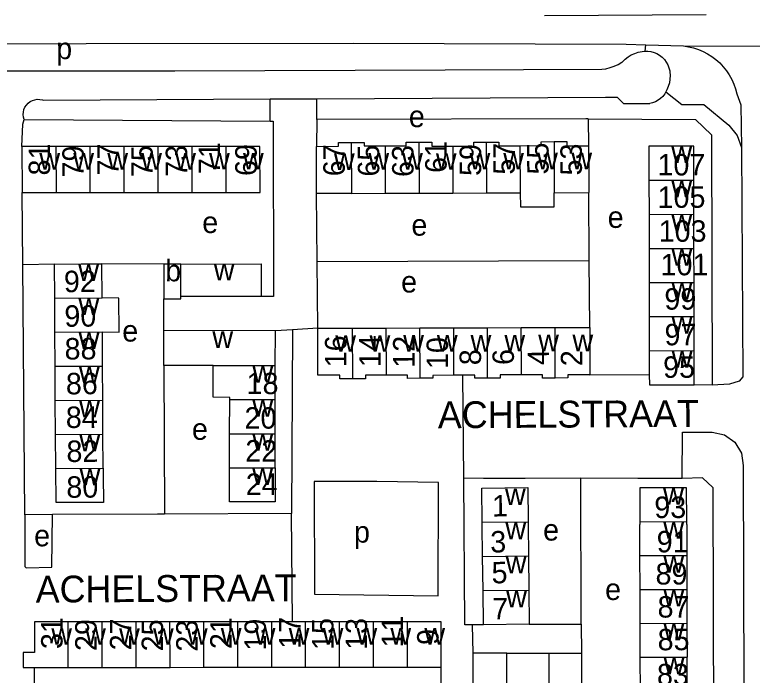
# Model space of a CAD drawing. Extents: x 159675 to 162108, y 386471 to 388472.
# Drawn here: x 161164.4 to 161301.9, y 388221.9 to 388345 of the extents above; entities that cross this region are included whole.
import ezdxf

# ---------------------------------------------------------------- set-up
doc = ezdxf.new("R2010")
doc.units = 0
for name, color, linetype in [('BLT_Basislijn', 7, 'Continuous'), ('BLT_Bebouwing', 7, 'Continuous'), ('BLT_Centroide', 7, 'Continuous'), ('BLT_Huisnummer', 7, 'Continuous'), ('BLT_Huisnummer_ tussenligend', 7, 'Continuous'), ('BLT_Onderverdeling_panden', 7, 'Continuous'), ('BLT_Straatnaam', 7, 'Continuous'), ('BLT_Vlakafsluiter', 7, 'Continuous')]:
    doc.layers.add(name, color=color, linetype=linetype)

msp = doc.modelspace()

# ---------------------------------------------------------------- linework, layer by layer
at = {"layer": 'BLT_Basislijn'}
for p, q in [((161293.3, 388345.05), (161263.18, 388344.84)), ((161281.95, 388338.24), (161282.06, 388339.43)), ((161153.34, 388334.61), (161194.24, 388334.61)), ((161194.24, 388334.61), (161244.64, 388334.75)), ((161244.64, 388334.75), (161273.85, 388334.89)), ((161169.72, 388329.12), (161211.99, 388329.34)), ((161211.99, 388329.34), (161220.74, 388329.39)), ((161212.01, 388325.2), (161211.99, 388329.34)), ((161220.73, 388325.5), (161220.74, 388329.39)), ((161299.8, 388328.26), (161299.92, 388320.28)), ((161166.12, 388325.5), (161212.01, 388325.2)), ((161220.73, 388325.5), (161220.64, 388320.5)), ((161271.33, 388325.65), (161271.4, 388320.63)), ((161165.91, 388298.38), (161165.75, 388311.87)), ((161220.78, 388299.02), (161220.67, 388311.7)), ((161271.53, 388299.19), (161271.44, 388311.89)), ((161220.78, 388299.02), (161271.53, 388299.19)), ((161271.62, 388286.74), (161271.53, 388299.19)), ((161171.79, 388298.55), (161165.91, 388298.38)), ((161166.27, 388251.79), (161165.91, 388298.38)), ((161192.21, 388298.55), (161180.64, 388298.61)), ((161220.89, 388286.58), (161220.78, 388299.02)), ((161192.18, 388286.17), (161192.21, 388292.1)), ((161216.16, 388286.31), (161212.98, 388286.13)), ((161216.16, 388286.31), (161215.97, 388252.04)), ((161220.89, 388286.58), (161216.16, 388286.31)), ((161192.17, 388279.66), (161192.31, 388251.92)), ((161248.15, 388258.62), (161247.97, 388277.82)), ((161271.65, 388277.89), (161282.72, 388277.96)), ((161270.02, 388231.38), (161269.95, 388258.66)), ((161292.65, 388258.67), (161288.86, 388258.59)), ((161171.42, 388251.85), (161166.27, 388251.79)), ((161215.97, 388252.04), (161192.31, 388251.92)), ((161216.18, 388231.83), (161215.97, 388252.04)), ((161251.78, 388231.31), (161249.7, 388231.29)), ((161249.7, 388231.29), (161249.79, 388226)), ((161260.34, 388231.38), (161270.02, 388231.38)), ((161270.02, 388231.38), (161270.05, 388226)), ((161256.15, 388226.02), (161264.07, 388225.98)), ((161168.09, 388213.23), (161168.04, 388223.34)), ((161243.93, 388213.45), (161243.92, 388223.38))]:
    msp.add_line(p, q, dxfattribs=at)
for points in [[(161054.52, 388339.48), (161177.68, 388339.69), (161227.49, 388339.76), (161278.41, 388339.53), (161282.06, 388339.43)], [(161282.06, 388339.43), (161289.09, 388339.27)], [(161289.09, 388339.27), (161290.04, 388339.08), (161290.96, 388338.87), (161291.87, 388338.58), (161292.75, 388338.21), (161293.59, 388337.77), (161294.39, 388337.26), (161295.15, 388336.68), (161295.86, 388336.05), (161296.51, 388335.36), (161297.1, 388334.61), (161297.63, 388333.82), (161298.09, 388332.98), (161298.47, 388332.11), (161298.79, 388331.21), (161299.02, 388330.29), (161299.8, 388328.26)], [(161277.7, 388336.26), (161278.21, 388336.75), (161278.76, 388337.18), (161279.36, 388337.54), (161280, 388337.83), (161280.67, 388338.05), (161281.36, 388338.19), (161281.95, 388338.24)], [(161281.95, 388338.24), (161282.06, 388338.25), (161282.43, 388338.25)], [(161282.43, 388338.25), (161283.02, 388338.18), (161283.6, 388338.02), (161284.14, 388337.8), (161284.65, 388337.5), (161285.12, 388337.13), (161285.54, 388336.71), (161285.89, 388336.23), (161286.18, 388335.71), (161286.39, 388335.16), (161286.52, 388334.58), (161286.55, 388334.41)], [(161273.85, 388334.89), (161274.64, 388334.99), (161275.42, 388335.18), (161276.17, 388335.44), (161276.9, 388335.78), (161277.58, 388336.18), (161277.7, 388336.26)], [(161286.55, 388334.41), (161286.6, 388333.71), (161286.57, 388333.02), (161286.46, 388332.33), (161286.27, 388331.66), (161286.01, 388331.02), (161285.82, 388330.68)], [(161220.74, 388329.39), (161274.53, 388329.67), (161276.73, 388329.67), (161277.93, 388328.51), (161282.85, 388328.5)], [(161285.59, 388330.29), (161285.24, 388329.83), (161284.82, 388329.43), (161284.36, 388329.09), (161283.85, 388328.81), (161283.31, 388328.61), (161282.85, 388328.5)], [(161285.82, 388330.68), (161285.67, 388330.41), (161285.59, 388330.29)], [(161285.82, 388330.68), (161288.8, 388328.3), (161292.92, 388328.3), (161297.57, 388324.46), (161299.12, 388322.52), (161299.92, 388320.28)], [(161166.12, 388325.5), (161166, 388325.96), (161165.95, 388326.43), (161165.99, 388326.9), (161166.1, 388327.36), (161166.29, 388327.8), (161166.55, 388328.2), (161166.87, 388328.55), (161167.25, 388328.84), (161167.67, 388329.06), (161168.12, 388329.21), (161168.59, 388329.28), (161169.06, 388329.27), (161169.53, 388329.18), (161169.72, 388329.12)], [(161165.73, 388320.47), (161165.88, 388324.64), (161166.12, 388325.5)], [(161271.33, 388325.65), (161270.88, 388325.65), (161220.73, 388325.5)], [(161271.33, 388325.65), (161291.32, 388325.5), (161294.35, 388322.65), (161294.47, 388275.98), (161291.09, 388276.06)], [(161212.01, 388325.2), (161212.55, 388325.2), (161212.63, 388292.53), (161210.32, 388292.53)], [(161299.92, 388320.28), (161300.19, 388277.5), (161299.49, 388276.72), (161297.7, 388276.16), (161294.47, 388275.98)], [(161288.86, 388258.59), (161288.91, 388267.21), (161294.45, 388267.2)], [(161294.45, 388267.2), (161296.75, 388266.73), (161298.68, 388265.37), (161299.94, 388263.27), (161300.23, 388261.02), (161300.41, 388198.39)], [(161231.88, 388258.02), (161220.21, 388258.01), (161220.31, 388237), (161243.32, 388236.68), (161243.41, 388257.82), (161231.88, 388258.02)], [(161269.95, 388258.66), (161259.58, 388258.55), (161251.77, 388258.58), (161248.15, 388258.62)], [(161249.7, 388231.29), (161248.33, 388231.28), (161248.15, 388258.62)], [(161288.86, 388258.59), (161280.59, 388258.55), (161269.95, 388258.66)], [(161292.65, 388258.67), (161294.56, 388256.87), (161294.67, 388212.59), (161289.81, 388212.61)], [(161166.27, 388251.79), (161166.29, 388242.14), (161166.51, 388241.88), (161171.3, 388242.04), (161171.42, 388251.85)], [(161192.31, 388251.92), (161190.98, 388251.91), (161171.42, 388251.85)]]:
    msp.add_lwpolyline(points, dxfattribs=at)
at = {"layer": 'BLT_Bebouwing'}
for p, q in [((161172.13, 388320.47), (161165.73, 388320.47)), ((161165.73, 388320.47), (161165.75, 388311.87)), ((161178.47, 388320.47), (161172.13, 388320.47)), ((161184.8, 388320.48), (161178.47, 388320.47)), ((161191.13, 388320.48), (161184.8, 388320.48)), ((161197.46, 388320.48), (161191.13, 388320.48)), ((161203.79, 388320.49), (161197.46, 388320.48)), ((161220.67, 388311.7), (161220.64, 388320.5)), ((161282.65, 388314.18), (161282.67, 388307.82)), ((161291.03, 388307.84), (161291.02, 388314.19)), ((161165.75, 388311.87), (161172.14, 388311.87)), ((161172.14, 388311.87), (161178.47, 388311.88)), ((161178.47, 388311.88), (161184.8, 388311.88)), ((161184.8, 388311.88), (161191.13, 388311.88)), ((161191.13, 388311.88), (161197.47, 388311.89)), ((161197.47, 388311.89), (161203.8, 388311.89)), ((161227.19, 388311.73), (161233.49, 388311.75)), ((161233.49, 388311.75), (161239.8, 388311.77)), ((161239.8, 388311.77), (161246.09, 388311.79)), ((161246.09, 388311.79), (161252.36, 388311.82)), ((161252.36, 388311.82), (161258.64, 388311.84)), ((161264.98, 388311.86), (161271.44, 388311.89)), ((161282.67, 388307.82), (161282.68, 388301.47)), ((161291.05, 388301.48), (161291.03, 388307.84)), ((161282.68, 388301.47), (161282.69, 388295.11)), ((161291.06, 388295.13), (161291.05, 388301.48)), ((161171.83, 388292.19), (161171.79, 388298.55)), ((161180.68, 388292.25), (161180.64, 388298.61)), ((161195.35, 388298.56), (161192.21, 388298.55)), ((161192.21, 388298.55), (161192.21, 388292.1)), ((161282.69, 388295.11), (161282.7, 388288.75)), ((161291.07, 388288.77), (161291.06, 388295.13)), ((161210.32, 388292.53), (161195.37, 388292.51)), ((161171.87, 388285.84), (161171.83, 388292.19)), ((161282.7, 388288.75), (161282.72, 388282.4)), ((161291.08, 388282.41), (161291.07, 388288.77)), ((161171.91, 388279.49), (161171.87, 388285.84)), ((161180.76, 388279.54), (161180.72, 388285.9)), ((161212.98, 388286.13), (161192.18, 388286.17)), ((161212.96, 388279.62), (161212.98, 388286.13)), ((161227.38, 388286.6), (161233.67, 388286.62)), ((161233.67, 388286.62), (161239.94, 388286.64)), ((161239.94, 388286.64), (161246.24, 388286.66)), ((161246.24, 388286.66), (161252.53, 388286.68)), ((161252.53, 388286.68), (161258.84, 388286.7)), ((161258.84, 388286.7), (161265.14, 388286.72)), ((161265.14, 388286.72), (161271.62, 388286.74)), ((161282.72, 388282.4), (161282.72, 388277.96)), ((161291.09, 388276.06), (161291.08, 388282.41)), ((161171.95, 388273.13), (161171.91, 388279.49)), ((161180.8, 388273.19), (161180.76, 388279.54)), ((161201.4, 388279.64), (161192.17, 388279.66)), ((161212.95, 388273.27), (161212.96, 388279.62)), ((161247.97, 388277.82), (161246.27, 388277.82)), ((161171.99, 388266.78), (161171.95, 388273.13)), ((161180.84, 388266.84), (161180.8, 388273.19)), ((161204.46, 388266.92), (161204.47, 388273.28)), ((161212.94, 388266.91), (161212.95, 388273.27)), ((161172.04, 388260.42), (161171.99, 388266.78)), ((161180.89, 388260.48), (161180.84, 388266.84)), ((161204.45, 388260.57), (161204.46, 388266.92)), ((161212.93, 388260.55), (161212.94, 388266.91)), ((161251.57, 388250), (161251.57, 388250.4)), ((161251.64, 388244.04), (161251.57, 388250)), ((161260.13, 388250.49), (161260.13, 388250)), ((161260.13, 388250), (161260.2, 388244.13)), ((161280.95, 388250.49), (161280.95, 388250)), ((161280.97, 388244.18), (161280.95, 388250)), ((161289.69, 388250), (161289.69, 388250.52)), ((161289.69, 388250), (161289.71, 388244.2)), ((161280.99, 388237.86), (161280.97, 388244.18)), ((161289.71, 388244.2), (161289.73, 388237.88)), ((161251.71, 388237.68), (161251.64, 388244.04)), ((161260.2, 388244.13), (161260.27, 388237.77)), ((161251.78, 388231.31), (161251.71, 388237.68)), ((161260.27, 388237.77), (161260.34, 388231.38)), ((161281.01, 388231.54), (161280.99, 388237.86)), ((161289.73, 388237.88), (161289.75, 388231.57)), ((161180.68, 388231.82), (161174.36, 388231.82)), ((161187.01, 388231.82), (161180.68, 388231.82)), ((161193.33, 388231.82), (161187.01, 388231.82)), ((161199.65, 388231.83), (161193.33, 388231.82)), ((161205.98, 388231.83), (161199.65, 388231.83)), ((161212.3, 388231.83), (161205.98, 388231.83)), ((161216.18, 388231.83), (161212.3, 388231.83)), ((161218.63, 388231.84), (161216.18, 388231.83)), ((161224.95, 388231.84), (161218.63, 388231.84)), ((161231.27, 388231.84), (161224.95, 388231.84)), ((161237.6, 388231.84), (161231.27, 388231.84)), ((161260.34, 388231.38), (161251.78, 388231.31)), ((161281.03, 388225.22), (161281.01, 388231.54)), ((161289.75, 388231.57), (161289.77, 388225.25)), ((161256.15, 388226.02), (161249.79, 388226)), ((161249.79, 388226), (161249.84, 388208.43)), ((161264.07, 388225.98), (161270.05, 388226)), ((161270.05, 388226), (161270.12, 388212.73)), ((161281.05, 388218.9), (161281.03, 388225.22)), ((161289.79, 388218.93), (161289.77, 388225.25)), ((161168.04, 388223.34), (161174.36, 388223.35)), ((161174.36, 388223.35), (161180.69, 388223.35)), ((161180.69, 388223.35), (161187.01, 388223.35)), ((161187.01, 388223.35), (161193.34, 388223.35)), ((161193.34, 388223.35), (161199.66, 388223.36)), ((161199.66, 388223.36), (161205.98, 388223.36)), ((161205.98, 388223.36), (161212.31, 388223.36)), ((161212.31, 388223.36), (161218.63, 388223.37)), ((161218.63, 388223.37), (161224.96, 388223.37)), ((161224.96, 388223.37), (161231.28, 388223.37)), ((161231.28, 388223.37), (161237.6, 388223.37)), ((161237.6, 388223.37), (161243.92, 388223.38))]:
    msp.add_line(p, q, dxfattribs=at)
for points in [[(161220.64, 388320.5), (161224.78, 388320.52), (161224.77, 388321.23), (161227.15, 388321.24)], [(161227.15, 388321.24), (161229.53, 388321.24), (161229.53, 388320.58), (161233.46, 388320.6)], [(161233.46, 388320.6), (161237.4, 388320.61), (161237.39, 388321.27), (161239.77, 388321.27)], [(161239.77, 388321.27), (161242.14, 388321.28), (161242.14, 388320.54), (161246.06, 388320.55)], [(161246.06, 388320.55), (161249.98, 388320.57), (161249.98, 388321.29), (161252.32, 388321.3)], [(161252.32, 388321.3), (161254.67, 388321.3), (161254.68, 388320.61), (161258.6, 388320.63)], [(161258.6, 388320.63), (161262.53, 388320.64), (161262.53, 388321.37), (161264.95, 388321.38)], [(161264.95, 388321.38), (161267.37, 388321.38), (161267.37, 388320.61), (161271.4, 388320.63)], [(161203.8, 388311.89), (161210.13, 388311.89), (161210.12, 388320.49), (161203.79, 388320.49)], [(161271.4, 388320.63), (161271.42, 388315.63), (161271.44, 388311.89)], [(161291.02, 388314.19), (161291.01, 388320.55), (161282.64, 388320.53), (161282.65, 388314.18)], [(161227.19, 388311.73), (161225.67, 388311.72), (161220.67, 388311.7)], [(161258.64, 388311.84), (161258.69, 388309.22), (161265.01, 388309.25), (161264.98, 388311.86)], [(161171.79, 388298.55), (161176.79, 388298.58), (161180.64, 388298.61)], [(161195.35, 388298.56), (161210.32, 388298.57), (161210.32, 388292.53)], [(161192.21, 388292.1), (161195.37, 388292.1), (161195.37, 388292.51)], [(161180.72, 388285.9), (161183.84, 388285.86), (161183.8, 388292.17), (161180.68, 388292.25)], [(161192.17, 388279.66), (161192.18, 388281.17), (161192.18, 388286.17)], [(161220.89, 388286.58), (161225.89, 388286.59), (161227.38, 388286.6)], [(161227.41, 388277.17), (161225.03, 388277.17), (161225.02, 388277.83), (161220.92, 388277.81), (161220.89, 388286.58)], [(161271.62, 388286.74), (161271.64, 388282.89), (161271.65, 388277.89)], [(161204.47, 388273.28), (161204.47, 388273.7), (161201.39, 388273.71), (161201.4, 388279.64)], [(161233.7, 388277.82), (161229.79, 388277.81), (161229.8, 388277.18), (161227.41, 388277.17)], [(161239.98, 388277.25), (161237.61, 388277.24), (161237.61, 388277.84), (161233.7, 388277.82)], [(161246.27, 388277.82), (161242.34, 388277.8), (161242.34, 388277.26), (161239.98, 388277.25)], [(161252.56, 388277.26), (161250.19, 388277.26), (161250.19, 388277.83), (161247.97, 388277.82)], [(161258.87, 388277.89), (161254.92, 388277.88), (161254.92, 388277.27), (161252.56, 388277.26)], [(161265.17, 388277.3), (161262.82, 388277.29), (161262.82, 388277.91), (161258.87, 388277.89)], [(161271.65, 388277.89), (161267.52, 388277.87), (161267.52, 388277.31), (161265.17, 388277.3)], [(161282.72, 388277.96), (161282.73, 388276.04), (161291.09, 388276.06)], [(161180.89, 388260.48), (161180.89, 388259.12), (161180.93, 388254.12), (161172.08, 388254.07), (161172.04, 388260.42)], [(161212.93, 388260.55), (161212.92, 388254.19), (161204.44, 388254.21), (161204.45, 388259.21), (161204.45, 388260.57)], [(161251.57, 388250.4), (161251.5, 388256.76), (161260.06, 388256.86), (161260.13, 388250.49)], [(161289.69, 388250.52), (161289.67, 388256.84), (161280.93, 388256.81), (161280.95, 388250.49)], [(161174.36, 388231.82), (161168.04, 388231.81), (161168.04, 388226.12), (161165.94, 388226.12), (161165.95, 388223.34), (161168.04, 388223.34)], [(161243.92, 388223.38), (161243.92, 388231.85), (161237.6, 388231.84)], [(161249.84, 388208.43), (161256.2, 388208.45), (161256.15, 388226.02)], [(161270.12, 388212.73), (161270.13, 388210.97), (161264.12, 388210.95), (161264.07, 388225.98)]]:
    msp.add_lwpolyline(points, dxfattribs=at)
at = {"layer": 'BLT_Onderverdeling_panden'}
for p, q in [((161227.15, 388321.24), (161227.19, 388311.73)), ((161239.77, 388321.27), (161239.8, 388311.77)), ((161252.32, 388321.3), (161252.36, 388311.82)), ((161264.95, 388321.38), (161264.98, 388311.86)), ((161172.14, 388311.87), (161172.13, 388320.47)), ((161178.47, 388311.88), (161178.47, 388320.47)), ((161184.8, 388311.88), (161184.8, 388320.48)), ((161191.13, 388311.88), (161191.13, 388320.48)), ((161197.47, 388311.89), (161197.46, 388320.48)), ((161203.8, 388311.89), (161203.79, 388320.49)), ((161233.46, 388320.6), (161233.49, 388311.75)), ((161246.06, 388320.55), (161246.09, 388311.79)), ((161258.6, 388320.63), (161258.64, 388311.84)), ((161282.65, 388314.18), (161291.02, 388314.19)), ((161282.67, 388307.82), (161291.03, 388307.84)), ((161282.68, 388301.47), (161291.05, 388301.48)), ((161195.37, 388292.51), (161195.35, 388298.56)), ((161282.69, 388295.11), (161291.06, 388295.13)), ((161171.83, 388292.19), (161180.68, 388292.25)), ((161282.7, 388288.75), (161291.07, 388288.77)), ((161171.87, 388285.84), (161180.72, 388285.9)), ((161227.41, 388277.17), (161227.38, 388286.6)), ((161233.7, 388277.82), (161233.67, 388286.62)), ((161239.98, 388277.25), (161239.94, 388286.64)), ((161246.27, 388277.82), (161246.24, 388286.66)), ((161252.56, 388277.26), (161252.53, 388286.68)), ((161258.87, 388277.89), (161258.84, 388286.7)), ((161265.17, 388277.3), (161265.14, 388286.72)), ((161282.72, 388282.4), (161291.08, 388282.41)), ((161171.91, 388279.49), (161180.76, 388279.54)), ((161201.4, 388279.64), (161212.96, 388279.62)), ((161171.95, 388273.13), (161180.8, 388273.19)), ((161204.47, 388273.28), (161212.95, 388273.27)), ((161171.99, 388266.78), (161180.84, 388266.84)), ((161204.46, 388266.92), (161212.94, 388266.91)), ((161172.04, 388260.42), (161180.89, 388260.48)), ((161204.45, 388260.57), (161212.93, 388260.55)), ((161251.57, 388250.4), (161260.13, 388250.49)), ((161280.95, 388250.49), (161289.69, 388250.52)), ((161280.97, 388244.18), (161289.71, 388244.2)), ((161251.64, 388244.04), (161260.2, 388244.13)), ((161251.71, 388237.68), (161260.27, 388237.77)), ((161280.99, 388237.86), (161289.73, 388237.88)), ((161174.36, 388223.35), (161174.36, 388231.82)), ((161180.69, 388223.35), (161180.68, 388231.82)), ((161187.01, 388223.35), (161187.01, 388231.82)), ((161193.34, 388223.35), (161193.33, 388231.82)), ((161199.66, 388223.36), (161199.65, 388231.83)), ((161205.98, 388223.36), (161205.98, 388231.83)), ((161212.31, 388223.36), (161212.3, 388231.83)), ((161218.63, 388223.37), (161218.63, 388231.84)), ((161224.96, 388223.37), (161224.95, 388231.84)), ((161231.28, 388223.37), (161231.27, 388231.84)), ((161237.6, 388223.37), (161237.6, 388231.84)), ((161281.01, 388231.54), (161289.75, 388231.57)), ((161281.03, 388225.22), (161289.77, 388225.25))]:
    msp.add_line(p, q, dxfattribs=at)
at = {"layer": 'BLT_Vlakafsluiter'}
msp.add_lwpolyline([(161289.09, 388339.27), (161311.49, 388339.16)], dxfattribs=at)

# ---------------------------------------------------------------- texts
at = {"layer": 'BLT_Centroide'}
for s, p in [('p', (161172.12, 388336.77)), ('e', (161237.88, 388324.09)), ('w', (161286.83, 388317.38)), ('w', (161168.97, 388316.17)), ('w', (161175.3, 388316.17)), ('w', (161181.64, 388316.17)), ('w', (161187.97, 388316.17)), ('w', (161194.3, 388316.17)), ('w', (161200.62, 388316.19)), ('w', (161206.95, 388316.19)), ('w', (161223.91, 388316.11)), ('w', (161230.33, 388316.17)), ('w', (161236.62, 388316.17)), ('w', (161242.92, 388316.16)), ('w', (161249.2, 388316.19)), ('w', (161255.48, 388316.22)), ('w', (161261.8, 388316.23)), ('w', (161268.19, 388316.25)), ('w', (161286.84, 388311)), ('e', (161199.35, 388304.34)), ('e', (161274.96, 388305.3)), ('w', (161286.85, 388304.66)), ('e', (161238.36, 388303.85)), ('w', (161286.87, 388298.28)), ('b', (161192.45, 388295.33)), ('w', (161176.23, 388295.41)), ('w', (161201.5, 388295.53)), ('e', (161236.44, 388293.25)), ('w', (161286.88, 388291.94)), ('w', (161176.27, 388289.03)), ('w', (161286.89, 388285.59)), ('e', (161184.43, 388284.1)), ('w', (161176.31, 388282.69)), ('w', (161201.24, 388282.91)), ('w', (161224.16, 388282.2)), ('w', (161230.55, 388282.2)), ('w', (161236.83, 388282.23)), ('w', (161243.11, 388282.23)), ('w', (161249.39, 388282.23)), ('w', (161255.7, 388282.28)), ('w', (161262, 388282.31)), ('w', (161268.39, 388282.3)), ('w', (161286.91, 388279.22)), ('w', (161176.36, 388276.34)), ('w', (161208.72, 388276.44)), ('w', (161176.4, 388269.97)), ('w', (161208.71, 388270.09)), ('e', (161197.43, 388265.79)), ('w', (161176.44, 388263.62)), ('w', (161208.7, 388263.75)), ('w', (161176.48, 388257.28)), ('w', (161208.68, 388257.38)), ('w', (161255.81, 388253.62)), ('w', (161285.3, 388253.66)), ('p', (161227.65, 388246.61)), ('w', (161255.89, 388247.25)), ('e', (161262.92, 388246.99)), ('w', (161285.34, 388247.34)), ('e', (161168, 388245.92)), ('w', (161255.95, 388240.91)), ('w', (161285.35, 388241.03)), ('e', (161274.48, 388235.91)), ('w', (161256.03, 388234.53)), ('w', (161285.37, 388234.72)), ('w', (161171.2, 388227.58)), ('w', (161177.52, 388227.58)), ('w', (161183.84, 388227.58)), ('w', (161190.17, 388227.58)), ('w', (161196.5, 388227.58)), ('w', (161202.81, 388227.59)), ('w', (161209.14, 388227.61)), ('w', (161215.47, 388227.61)), ('w', (161221.8, 388227.61)), ('w', (161228.11, 388227.61)), ('w', (161234.44, 388227.61)), ('w', (161240.77, 388227.61)), ('w', (161285.38, 388228.41)), ('w', (161285.41, 388222.06))]:
    msp.add_text(s, height=4, dxfattribs=at).set_placement(p)
at = {"layer": 'BLT_Huisnummer'}
for s, rotation, p in [('61', 90.2073, (161244.93, 388315.56)), ('81', 90.0267, (161170.98, 388315.08)), ('77', 90.0267, (161183.79, 388315.08)), ('73', 90.0267, (161196.54, 388314.81)), ('69', 90.0267, (161209.5, 388314.98)), ('67', 90.2019, (161225.93, 388314.94)), ('57', 90.2028, (161257.66, 388315.23)), ('53', 90.2087, (161270.16, 388315.08)), ('107', 0.1096, (161284.25, 388315.07)), ('103', 0.1096, (161284.47, 388302.7)), ('92', 0.3755, (161173.56, 388293.3)), ('99', 0.1096, (161285.54, 388290.05)), ('88', 0.3755, (161173.69, 388280.75)), ('16', 90.1897, (161226.25, 388279.31)), ('10', 90.1889, (161245.2, 388279)), ('6', 90.1825, (161257.48, 388279.74)), ('2', 90.1946, (161270.23, 388279.52)), ('95', 0.1096, (161285.3, 388277.34)), ('18', 359.8987, (161207.62, 388274.31)), ('84', 0.3756, (161173.92, 388267.98)), ('24', 359.8987, (161207.46, 388255.51)), ('80', 0.3755, (161174.02, 388254.97)), ('1', 0.6358, (161253.43, 388251.47)), ('93', 0.1771, (161283.66, 388251.19)), ('89', 0.1771, (161283.89, 388238.79)), ('7', 0.6358, (161253.45, 388232.27)), ('31', 90.0271, (161173.3, 388226.76)), ('25', 90.0271, (161192.05, 388226.33)), ('21', 90.0271, (161204.83, 388226.76)), ('17', 90.0271, (161217.68, 388226.82)), ('13', 90.0271, (161230.09, 388226.61)), ('85', 0.1837, (161284.28, 388226.53)), ('9', 90.0271, (161243.42, 388227.54))]:
    msp.add_text(s, height=4, rotation=rotation, dxfattribs=at).set_placement(p)
at = {"layer": 'BLT_Huisnummer_ tussenligend'}
for s, rotation, p in [('79', 90.0267, (161177.26, 388314.7)), ('75', 90.0267, (161190.13, 388314.77)), ('71', 90.0267, (161202.69, 388315.32)), ('65', 90.2019, (161232.37, 388314.87)), ('63', 90.2169, (161238.76, 388314.8)), ('59', 90.205, (161251.37, 388314.99)), ('55', 90.2055, (161263.95, 388315.26)), ('105', 0.1096, (161284.27, 388309.03)), ('101', 0.1096, (161284.82, 388296.45)), ('90', 0.3755, (161173.65, 388286.86)), ('97', 0.1096, (161285.57, 388283.4)), ('14', 90.1897, (161232.62, 388279.34)), ('12', 90.1946, (161238.95, 388279.23)), ('8', 90.1953, (161251.35, 388279.7)), ('4', 90.1825, (161264.02, 388279.71)), ('86', 0.3756, (161173.93, 388274.25)), ('20', 359.8987, (161207.23, 388267.87)), ('82', 0.3755, (161174.04, 388261.64)), ('22', 359.8987, (161207.37, 388261.73)), ('3', 0.6358, (161253.08, 388244.76)), ('91', 0.1771, (161284.11, 388244.79)), ('5', 0.6358, (161253.33, 388239.01)), ('87', 0.1837, (161284.27, 388232.63)), ('29', 90.0271, (161179.65, 388226.39)), ('27', 90.0271, (161186.13, 388226.53)), ('23', 90.0271, (161198.49, 388226.28)), ('19', 90.0271, (161211.23, 388226.47)), ('15', 90.0271, (161223.83, 388226.6)), ('11', 90.0271, (161236.81, 388227.06)), ('83', 0.1837, (161284.16, 388220))]:
    msp.add_text(s, height=4, rotation=rotation, dxfattribs=at).set_placement(p)
at = {"layer": 'BLT_Straatnaam'}
for p in [(161243.3, 388267.93), (161168.3, 388235.42)]:
    msp.add_text('ACHELSTRAAT', height=5, rotation=0.3142, dxfattribs=at).set_placement(p)

doc.saveas('drawing.dxf')
